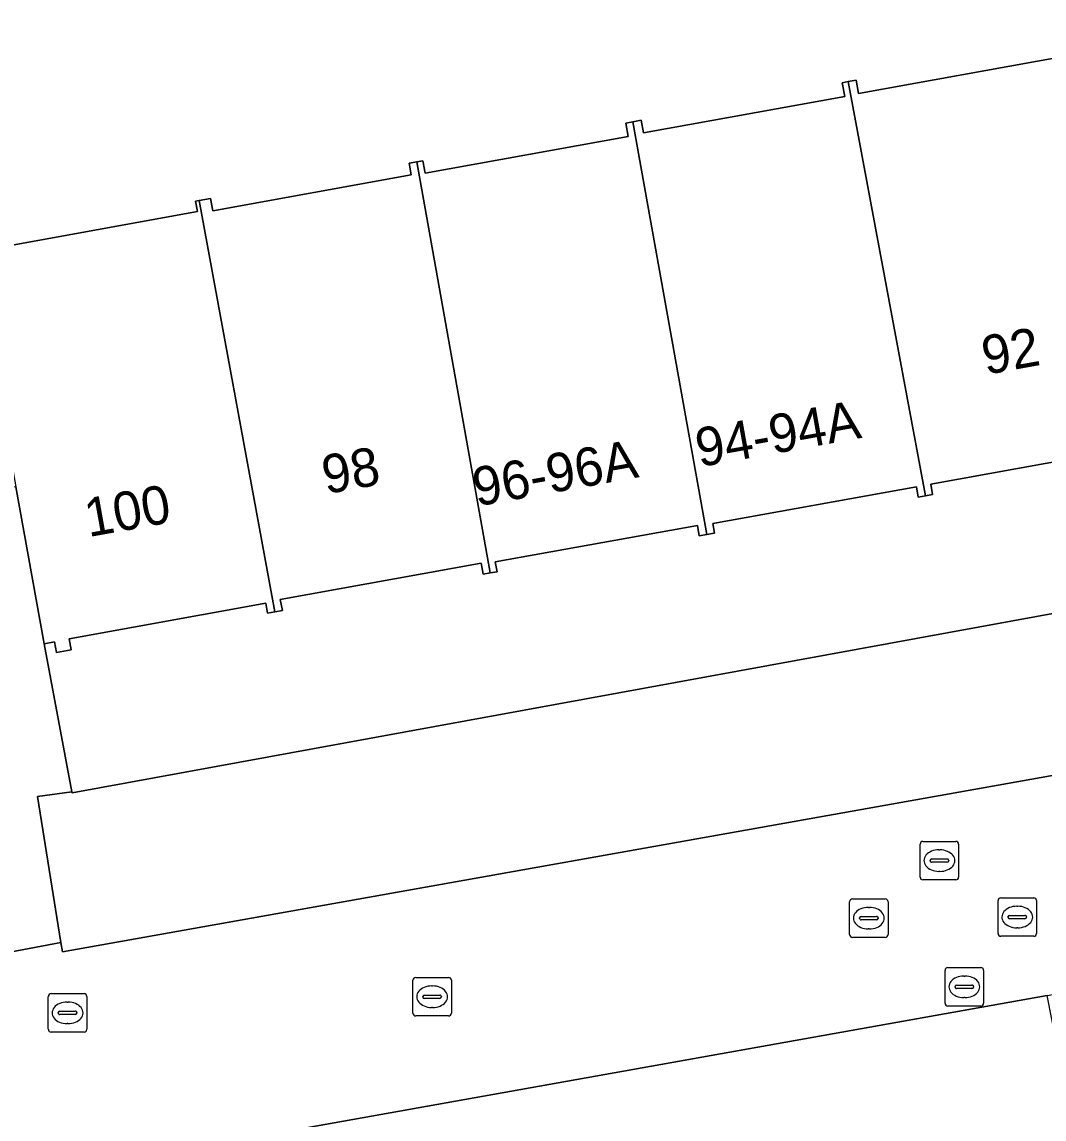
# Model space of a CAD drawing. Extents: x 157793 to 159380, y 380877 to 382313.
# Drawn here: x 158346.03 to 158372.58, y 381426.55 to 381455.05 of the extents above; entities that cross this region are included whole.
import ezdxf

# ---------------------------------------------------------------- set-up
doc = ezdxf.new("R2010")
doc.units = 0
for name, color, linetype in [('IMGEO_Erf', 7, 'Continuous'), ('IMGEO_Kolk', 7, 'Continuous'), ('IMGEO_Pand', 7, 'Continuous'), ('IMGEO_Pand_nummerreeks', 7, 'Continuous'), ('IMGEO_Parkeervlak_open', 7, 'Continuous'), ('IMGEO_Rijbaan_lokaal_open', 7, 'Continuous'), ('IMGEO_Rioolput', 7, 'Continuous'), ('IMGEO_Voetpad_open', 7, 'Continuous')]:
    doc.layers.add(name, color=color, linetype=linetype)

msp = doc.modelspace()

# ---------------------------------------------------------------- linework, layer by layer
at = {"layer": 'IMGEO_Erf'}
for points in [[(158345.381, 381449.188), (158350.584, 381450.126), (158350.534, 381450.396), (158350.631, 381450.413), (158350.927, 381450.467), (158350.984, 381450.148), (158356.142, 381451.078), (158356.087, 381451.385), (158356.285, 381451.421), (158356.443, 381451.449), (158356.501, 381451.128), (158361.773, 381452.079), (158361.711, 381452.425), (158361.899, 381452.459), (158362.116, 381452.498), (158362.175, 381452.171), (158367.401, 381453.114), (158367.336, 381453.474), (158367.489, 381453.502), (158367.695, 381453.539), (158367.757, 381453.196), (158373.029, 381454.146)], [(158374.86, 381443.99), (158369.636, 381443.048), (158369.685, 381442.774), (158369.497, 381442.74), (158369.311, 381442.706), (158369.262, 381442.979), (158363.974, 381442.025), (158364.019, 381441.775), (158363.82, 381441.739), (158363.622, 381441.703), (158363.573, 381441.975), (158358.322, 381441.028), (158358.369, 381440.771), (158358.187, 381440.739), (158358.005, 381440.706), (158357.953, 381440.993), (158352.739, 381440.053), (158352.792, 381439.761), (158352.6, 381439.726), (158352.41, 381439.692), (158352.363, 381439.952), (158347.252, 381439.031), (158347.303, 381438.744), (158346.922, 381438.676), (158346.873, 381438.948), (158346.606, 381438.9), (158347.326, 381435.057), (158347.332, 381435.023), (158352.398, 381435.95), (158353.628, 381436.175), (158387.301, 381442.337)]]:
    msp.add_lwpolyline(points, dxfattribs=at)
at = {"layer": 'IMGEO_Kolk'}
for p, q in [((158367.528, 381431.346), (158367.528, 381432.198)), ((158367.603, 381432.272), (158368.455, 381432.272)), ((158368.016, 381432.052), (158368.041, 381432.052)), ((158368.529, 381432.198), (158368.529, 381431.346)), ((158367.787, 381431.766), (158367.787, 381431.778)), ((158367.83, 381431.815), (158368.228, 381431.815)), ((158368.271, 381431.778), (158368.271, 381431.766)), ((158368.225, 381431.729), (158367.827, 381431.729)), ((158368.039, 381431.492), (158368.014, 381431.492)), ((158368.455, 381431.272), (158367.603, 381431.272)), ((158356.182, 381429.305), (158356.182, 381430.157)), ((158356.257, 381430.231), (158357.109, 381430.231)), ((158357.183, 381430.157), (158357.183, 381429.305)), ((158356.441, 381429.725), (158356.441, 381429.737)), ((158356.484, 381429.774), (158356.882, 381429.774)), ((158356.67, 381430.011), (158356.695, 381430.011)), ((158356.925, 381429.737), (158356.925, 381429.725)), ((158356.879, 381429.688), (158356.481, 381429.688)), ((158356.693, 381429.451), (158356.668, 381429.451)), ((158357.109, 381429.231), (158356.257, 381429.231))]:
    msp.add_line(p, q, dxfattribs=at)
for points in [[(158367.528, 381431.346), (158367.528, 381432.198)], [(158367.603, 381432.272), (158368.455, 381432.272)], [(158368.529, 381432.198), (158368.529, 381431.346)], [(158368.455, 381431.272), (158367.603, 381431.272)], [(158356.182, 381429.305), (158356.182, 381430.157)], [(158356.257, 381430.231), (158357.109, 381430.231)], [(158357.183, 381430.157), (158357.183, 381429.305)], [(158357.109, 381429.231), (158356.257, 381429.231)]]:
    msp.add_lwpolyline(points, dxfattribs=at)
for centre, radius, start, end in [((158367.605, 381432.196), 0.0765, 91.552, 178.448), ((158367.605, 381432.196), 0.0765, 91.552, 178.448), ((158368.453, 381432.196), 0.0765, 1.552, 88.448), ((158368.453, 381432.196), 0.0765, 1.552, 88.448), ((158367.827, 381431.775), 0.0403, 85.8775, 175.7526), ((158367.824, 381431.765), 0.0366, 178.938, 274.7102), ((158368.228, 381431.772), 0.043, 264.8664, 352.4533), ((158368.232, 381431.777), 0.0386, 1.7309, 96.639), ((158367.605, 381431.348), 0.0765, 181.552, 268.448), ((158367.605, 381431.348), 0.0765, 181.552, 268.448), ((158368.453, 381431.348), 0.0765, 271.552, 358.448), ((158368.453, 381431.348), 0.0765, 271.552, 358.448), ((158356.259, 381430.155), 0.0765, 91.552, 178.448), ((158356.259, 381430.155), 0.0765, 91.552, 178.448), ((158357.107, 381430.155), 0.0765, 1.552, 88.448), ((158357.107, 381430.155), 0.0765, 1.552, 88.448), ((158356.481, 381429.734), 0.0403, 85.8775, 175.7526), ((158356.886, 381429.736), 0.0386, 1.7309, 96.639), ((158356.478, 381429.724), 0.0366, 178.938, 274.7102), ((158356.882, 381429.731), 0.043, 264.8664, 352.4533), ((158356.259, 381429.307), 0.0765, 181.552, 268.448), ((158356.259, 381429.307), 0.0765, 181.552, 268.448), ((158357.107, 381429.307), 0.0765, 271.552, 358.448), ((158357.107, 381429.307), 0.0765, 271.552, 358.448)]:
    msp.add_arc(centre, radius, start, end, dxfattribs=at)
for centre, major_axis, ratio, start_param, end_param in [((158368.015, 381431.772), (-0.387, 0.002), 0.722429, 4.712389, 7.853982), ((158368.04, 381431.772), (-0.39, 0.002), 0.717154, 1.570796, 4.712389), ((158356.669, 381429.731), (-0.387, 0.002), 0.722429, 4.712389, 7.853982), ((158356.694, 381429.731), (-0.39, 0.002), 0.717154, 1.570796, 4.712389)]:
    msp.add_ellipse(centre, major_axis=major_axis, ratio=ratio, start_param=start_param, end_param=end_param, dxfattribs=at)
at = {"layer": 'IMGEO_Pand'}
for points in [[(158373.079, 381454.549), (158372.96, 381454.527), (158373.029, 381454.146), (158367.757, 381453.196), (158367.695, 381453.539), (158367.489, 381453.502), (158369.497, 381442.74), (158369.685, 381442.774), (158369.636, 381443.048), (158374.86, 381443.99), (158374.907, 381443.728), (158375.115, 381443.765)], [(158367.489, 381453.502), (158367.336, 381453.474), (158367.401, 381453.114), (158362.175, 381452.171), (158362.116, 381452.498), (158361.899, 381452.459), (158363.82, 381441.739), (158364.019, 381441.775), (158363.974, 381442.025), (158369.262, 381442.979), (158369.311, 381442.706), (158369.497, 381442.74)], [(158361.899, 381452.459), (158361.711, 381452.425), (158361.773, 381452.079), (158356.501, 381451.128), (158356.443, 381451.449), (158356.285, 381451.421), (158358.187, 381440.739), (158358.369, 381440.771), (158358.322, 381441.028), (158363.573, 381441.975), (158363.622, 381441.703), (158363.82, 381441.739)], [(158356.285, 381451.421), (158356.087, 381451.385), (158356.142, 381451.078), (158350.984, 381450.148), (158350.927, 381450.467), (158350.631, 381450.413), (158352.6, 381439.726), (158352.792, 381439.761), (158352.739, 381440.053), (158357.953, 381440.993), (158358.005, 381440.706), (158358.187, 381440.739)], [(158350.631, 381450.413), (158350.534, 381450.396), (158350.584, 381450.126), (158345.381, 381449.188), (158345.328, 381449.481), (158344.955, 381449.414), (158345.006, 381449.13), (158344.769, 381449.087), (158345.871, 381442.976), (158346.606, 381438.9), (158346.873, 381438.948), (158346.922, 381438.676), (158347.303, 381438.744), (158347.252, 381439.031), (158352.363, 381439.952), (158352.41, 381439.692), (158352.6, 381439.726)]]:
    msp.add_lwpolyline(points, close=True, dxfattribs=at)
at = {"layer": 'IMGEO_Parkeervlak_open'}
msp.add_lwpolyline([(158373.513, 381424.892), (158373.135, 381427.348), (158372.662, 381429.759), (158353.167, 381426.285), (158354.039, 381421.408), (158366.649, 381423.721), (158366.593, 381424.003), (158368.732, 381424.401), (158368.797, 381424.08), (158369.231, 381424.147)], close=True, dxfattribs=at)
at = {"layer": 'IMGEO_Rijbaan_lokaal_open'}
for points in [[(158390.318, 381433.326), (158390.946, 381433.696), (158389.687, 381438.882), (158388.503, 381438.277), (158347.078, 381430.896), (158347.04, 381431.137), (158344.88, 381430.73)], [(158347.25, 381425.025), (158348.082, 381425.151), (158348.074, 381425.37), (158353.167, 381426.285), (158372.662, 381429.759), (158387.962, 381432.489)]]:
    msp.add_lwpolyline(points, dxfattribs=at)
at = {"layer": 'IMGEO_Rioolput'}
for p, q in [((158369.435, 381433.766), (158370.287, 381433.766)), ((158369.36, 381432.84), (158369.36, 381433.692)), ((158369.848, 381433.546), (158369.873, 381433.546)), ((158370.361, 381433.692), (158370.361, 381432.84)), ((158369.619, 381433.26), (158369.619, 381433.272)), ((158370.057, 381433.223), (158369.659, 381433.223)), ((158369.662, 381433.309), (158370.06, 381433.309)), ((158370.103, 381433.272), (158370.103, 381433.26)), ((158369.871, 381432.986), (158369.846, 381432.986)), ((158370.287, 381432.766), (158369.435, 381432.766)), ((158371.459, 381432.301), (158372.311, 381432.301)), ((158371.384, 381431.375), (158371.384, 381432.227)), ((158371.872, 381432.081), (158371.897, 381432.081)), ((158372.385, 381432.227), (158372.385, 381431.375)), ((158371.643, 381431.795), (158371.643, 381431.807)), ((158372.081, 381431.758), (158371.683, 381431.758)), ((158371.686, 381431.844), (158372.084, 381431.844)), ((158372.127, 381431.807), (158372.127, 381431.795)), ((158371.895, 381431.521), (158371.87, 381431.521)), ((158372.311, 381431.301), (158371.459, 381431.301)), ((158370.008, 381429.562), (158370.008, 381430.414)), ((158370.083, 381430.488), (158370.935, 381430.488)), ((158371.009, 381430.414), (158371.009, 381429.562)), ((158370.31, 381430.031), (158370.708, 381430.031)), ((158370.496, 381430.268), (158370.521, 381430.268)), ((158346.712, 381428.885), (158346.712, 381429.737)), ((158346.787, 381429.811), (158347.639, 381429.811)), ((158347.713, 381429.737), (158347.713, 381428.885)), ((158370.267, 381429.982), (158370.267, 381429.994)), ((158370.705, 381429.945), (158370.307, 381429.945)), ((158370.751, 381429.994), (158370.751, 381429.982)), ((158347.2, 381429.591), (158347.225, 381429.591)), ((158370.935, 381429.488), (158370.083, 381429.488)), ((158370.519, 381429.708), (158370.494, 381429.708)), ((158346.971, 381429.305), (158346.971, 381429.317)), ((158347.409, 381429.268), (158347.011, 381429.268)), ((158347.014, 381429.354), (158347.412, 381429.354)), ((158347.455, 381429.317), (158347.455, 381429.305)), ((158347.223, 381429.031), (158347.198, 381429.031)), ((158347.639, 381428.811), (158346.787, 381428.811))]:
    msp.add_line(p, q, dxfattribs=at)
for points in [[(158369.435, 381433.766), (158370.287, 381433.766)], [(158369.36, 381432.84), (158369.36, 381433.692)], [(158370.361, 381433.692), (158370.361, 381432.84)], [(158370.287, 381432.766), (158369.435, 381432.766)], [(158371.459, 381432.301), (158372.311, 381432.301)], [(158371.384, 381431.375), (158371.384, 381432.227)], [(158372.385, 381432.227), (158372.385, 381431.375)], [(158372.311, 381431.301), (158371.459, 381431.301)], [(158370.008, 381429.562), (158370.008, 381430.414)], [(158370.083, 381430.488), (158370.935, 381430.488)], [(158371.009, 381430.414), (158371.009, 381429.562)], [(158346.712, 381428.885), (158346.712, 381429.737)], [(158346.787, 381429.811), (158347.639, 381429.811)], [(158347.713, 381429.737), (158347.713, 381428.885)], [(158370.935, 381429.488), (158370.083, 381429.488)], [(158347.639, 381428.811), (158346.787, 381428.811)]]:
    msp.add_lwpolyline(points, dxfattribs=at)
for centre, radius, start, end in [((158369.437, 381433.69), 0.0765, 91.552, 178.448), ((158369.437, 381433.69), 0.0765, 91.552, 178.448), ((158370.285, 381433.69), 0.0765, 1.552, 88.448), ((158370.285, 381433.69), 0.0765, 1.552, 88.448), ((158369.659, 381433.269), 0.0403, 85.8775, 175.7526), ((158369.656, 381433.259), 0.0366, 178.938, 274.7102), ((158370.06, 381433.266), 0.043, 264.8664, 352.4533), ((158370.064, 381433.271), 0.0386, 1.7309, 96.639), ((158369.437, 381432.842), 0.0765, 181.552, 268.448), ((158369.437, 381432.842), 0.0765, 181.552, 268.448), ((158370.285, 381432.842), 0.0765, 271.552, 358.448), ((158370.285, 381432.842), 0.0765, 271.552, 358.448), ((158371.461, 381432.225), 0.0765, 91.552, 178.448), ((158371.461, 381432.225), 0.0765, 91.552, 178.448), ((158372.309, 381432.225), 0.0765, 1.552, 88.448), ((158372.309, 381432.225), 0.0765, 1.552, 88.448), ((158371.683, 381431.804), 0.0403, 85.8775, 175.7526), ((158371.68, 381431.794), 0.0366, 178.938, 274.7102), ((158372.084, 381431.801), 0.043, 264.8664, 352.4533), ((158372.088, 381431.806), 0.0386, 1.7309, 96.639), ((158371.461, 381431.377), 0.0765, 181.552, 268.448), ((158371.461, 381431.377), 0.0765, 181.552, 268.448), ((158372.309, 381431.377), 0.0765, 271.552, 358.448), ((158372.309, 381431.377), 0.0765, 271.552, 358.448), ((158370.085, 381430.412), 0.0765, 91.552, 178.448), ((158370.085, 381430.412), 0.0765, 91.552, 178.448), ((158370.933, 381430.412), 0.0765, 1.552, 88.448), ((158370.933, 381430.412), 0.0765, 1.552, 88.448), ((158370.307, 381429.991), 0.0403, 85.8775, 175.7526), ((158370.712, 381429.993), 0.0386, 1.7309, 96.639), ((158346.789, 381429.735), 0.0765, 91.552, 178.448), ((158346.789, 381429.735), 0.0765, 91.552, 178.448), ((158347.637, 381429.735), 0.0765, 1.552, 88.448), ((158347.637, 381429.735), 0.0765, 1.552, 88.448), ((158370.304, 381429.981), 0.0366, 178.938, 274.7102), ((158370.708, 381429.988), 0.043, 264.8664, 352.4533), ((158370.085, 381429.564), 0.0765, 181.552, 268.448), ((158370.085, 381429.564), 0.0765, 181.552, 268.448), ((158370.933, 381429.564), 0.0765, 271.552, 358.448), ((158370.933, 381429.564), 0.0765, 271.552, 358.448), ((158347.011, 381429.314), 0.0403, 85.8775, 175.7526), ((158347.008, 381429.304), 0.0366, 178.938, 274.7102), ((158347.412, 381429.311), 0.043, 264.8664, 352.4533), ((158347.416, 381429.316), 0.0386, 1.7309, 96.639), ((158346.789, 381428.887), 0.0765, 181.552, 268.448), ((158346.789, 381428.887), 0.0765, 181.552, 268.448), ((158347.637, 381428.887), 0.0765, 271.552, 358.448), ((158347.637, 381428.887), 0.0765, 271.552, 358.448)]:
    msp.add_arc(centre, radius, start, end, dxfattribs=at)
for centre, major_axis, ratio, start_param, end_param in [((158369.847, 381433.266), (-0.387, 0.002), 0.722429, 4.712389, 7.853982), ((158369.872, 381433.266), (-0.39, 0.002), 0.717154, 1.570796, 4.712389), ((158371.871, 381431.801), (-0.387, 0.002), 0.722429, 4.712389, 7.853982), ((158371.896, 381431.801), (-0.39, 0.002), 0.717154, 1.570796, 4.712389), ((158370.495, 381429.988), (-0.387, 0.002), 0.722429, 4.712389, 7.853982), ((158370.52, 381429.988), (-0.39, 0.002), 0.717154, 1.570796, 4.712389), ((158347.199, 381429.311), (-0.387, 0.002), 0.722429, 4.712389, 7.853982), ((158347.224, 381429.311), (-0.39, 0.002), 0.717154, 1.570796, 4.712389)]:
    msp.add_ellipse(centre, major_axis=major_axis, ratio=ratio, start_param=start_param, end_param=end_param, dxfattribs=at)
at = {"layer": 'IMGEO_Voetpad_open'}
msp.add_lwpolyline([(158344.88, 381430.73), (158347.04, 381431.137), (158346.431, 381434.929), (158347.326, 381435.057), (158346.606, 381438.9), (158345.871, 381442.976), (158344.185, 381442.728), (158337.485, 381456.187), (158336.797, 381457.569), (158336.768, 381457.628), (158326.548, 381478.159)], dxfattribs=at)
msp.add_lwpolyline([(158388.503, 381438.277), (158389.687, 381438.882), (158388.705, 381442.588), (158387.491, 381442.372), (158387.301, 381442.337), (158353.628, 381436.175), (158352.398, 381435.95), (158347.332, 381435.023), (158347.326, 381435.057), (158346.431, 381434.929), (158347.04, 381431.137), (158347.078, 381430.896)], close=True, dxfattribs=at)

# ---------------------------------------------------------------- texts
at = {"layer": 'IMGEO_Pand_nummerreeks'}
for s, rotation, p in [('92', 10.25, (158371.062, 381445.884)), ('94-94A', 10.2273, (158363.625, 381443.486)), ('98', 10.25, (158353.921, 381442.784)), ('96-96A', 10.2216, (158357.837, 381442.465)), ('100', 10.2502, (158347.753, 381441.668))]:
    msp.add_text(s, height=1, rotation=rotation, dxfattribs=at).set_placement(p)

doc.saveas('drawing.dxf')
